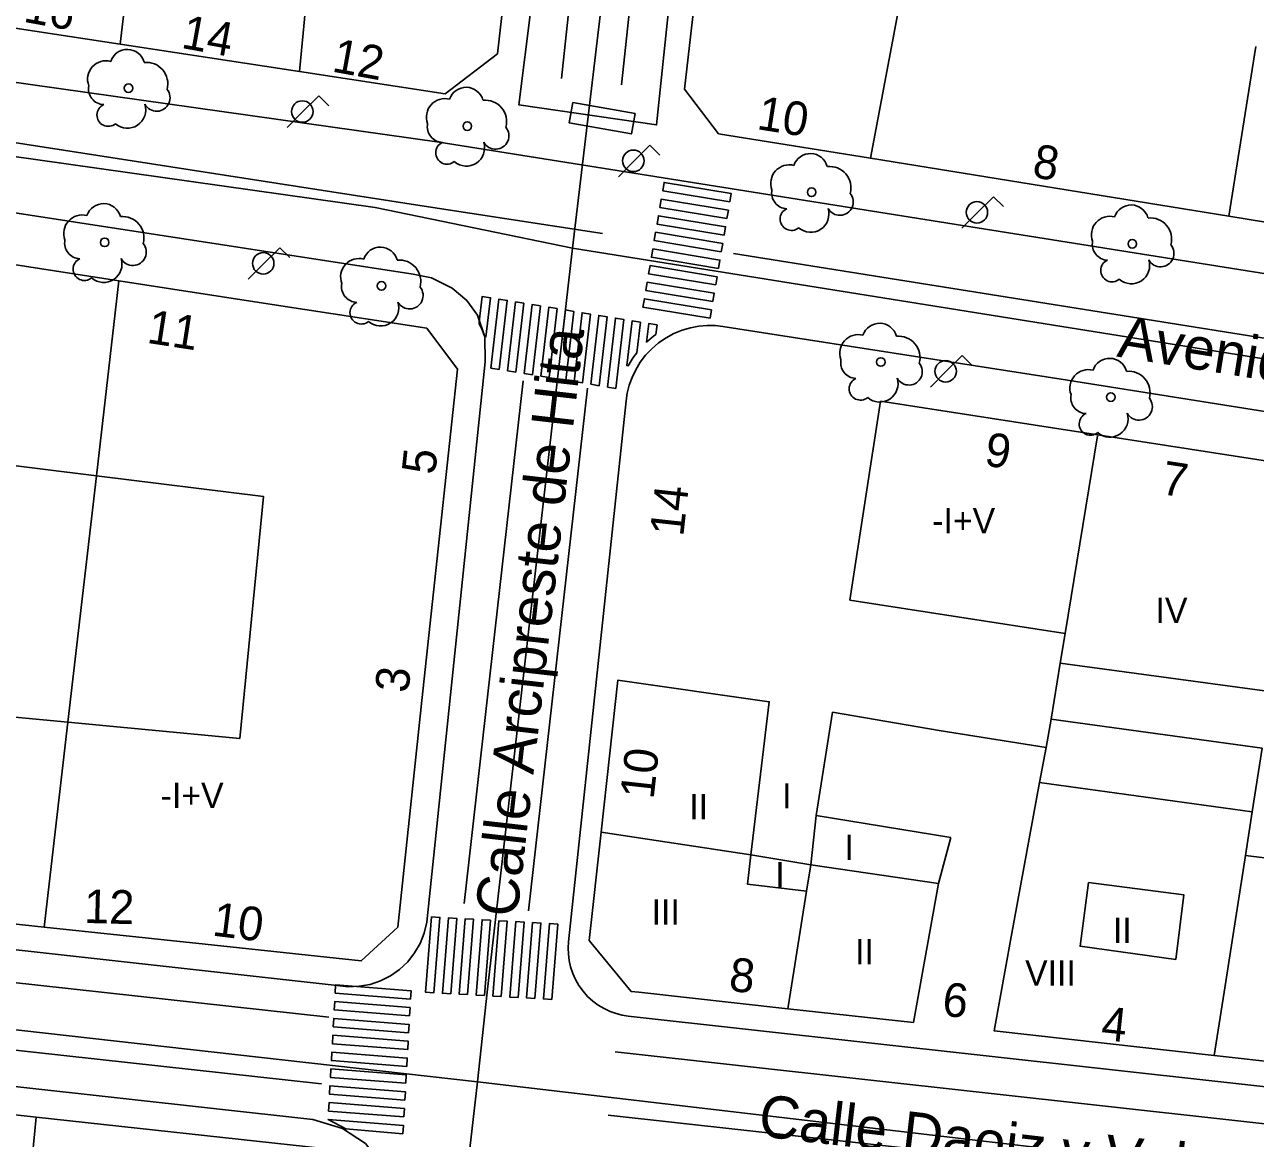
# Model space of a CAD drawing. Extents: x 282771 to 285132, y 4823109 to 4825496.
# Drawn here: x 283164.5 to 283237.5, y 4824286.9 to 4824352.9 of the extents above; entities that cross this region are included whole.
import ezdxf

# ---------------------------------------------------------------- set-up
doc = ezdxf.new("R2010")
doc.units = 0
for name, color, linetype in [('ACERA-BORDILLO', 7, 'Continuous'), ('ARBOL', 7, 'Continuous'), ('CALLE-EJE', 7, 'Continuous'), ('CALLE-TEXTO', 7, 'Continuous'), ('EDIFICIO', 7, 'Continuous'), ('EDIFICIO-PROYECTADO', 7, 'Continuous'), ('FAROLA', 7, 'Continuous'), ('INTERIOR-EDIFICIO', 7, 'Continuous'), ('MARQUESINA-BUS', 7, 'Continuous'), ('MEDIANERA', 7, 'Continuous'), ('NUM-LOCAL', 7, 'Continuous'), ('NUM-PORTAL', 7, 'Continuous'), ('NUM-VADO', 7, 'Continuous'), ('PASO-PEATONES', 7, 'Continuous'), ('SENAL-VIARIA', 7, 'Continuous'), ('TXT-ALTURA-EDIFICIO', 7, 'Continuous')]:
    doc.layers.add(name, color=color, linetype=linetype)

msp = doc.modelspace()

# ---------------------------------------------------------------- linework, layer by layer
at = {"layer": 'ACERA-BORDILLO'}
for points in [[(283204.257, 4824369.082), (283201.957, 4824346.992), (283193.797, 4824348.182), (283196.707, 4824371.452)], [(283127.812, 4824354.619), (283189.068, 4824345.967), (283271.518, 4824332.847)], [(283127.672, 4824347.349), (283187.515, 4824338.135), (283188.604, 4824337.924), (283189.834, 4824337.309), (283190.712, 4824336.571), (283191.327, 4824335.709), (283191.766, 4824334.427), (283191.783, 4824332.95), (283188.337, 4824299.711), (283188.177, 4824299.061), (283187.937, 4824298.451), (283187.607, 4824297.881), (283187.197, 4824297.361), (283186.717, 4824296.911), (283186.177, 4824296.531), (283185.587, 4824296.231), (283184.967, 4824296.021), (283184.317, 4824295.911), (283183.657, 4824295.881), (283183.007, 4824295.961), (283121.944, 4824302.739)], [(283249.853, 4824328.121), (283225.959, 4824331.907), (283205.895, 4824335.04), (283205.437, 4824335.09), (283204.959, 4824335.097), (283204.468, 4824335.057), (283203.971, 4824334.965), (283203.474, 4824334.82), (283202.988, 4824334.621), (283202.519, 4824334.368), (283202.078, 4824334.065), (283201.672, 4824333.717), (283201.307, 4824333.33), (283200.989, 4824332.912), (283200.721, 4824332.469), (283200.504, 4824332.012), (283200.338, 4824331.548), (283200.222, 4824331.085), (283200.152, 4824330.629)], [(283200.152, 4824330.629), (283196.735, 4824298.541), (283196.713, 4824298.183), (283196.724, 4824297.812), (283196.771, 4824297.433), (283196.857, 4824297.051), (283196.983, 4824296.672), (283197.149, 4824296.301), (283197.353, 4824295.946), (283197.595, 4824295.611), (283197.869, 4824295.304), (283198.172, 4824295.027), (283198.498, 4824294.786), (283198.842, 4824294.582), (283199.197, 4824294.416), (283199.556, 4824294.288), (283199.916, 4824294.197), (283200.271, 4824294.142), (283249.697, 4824288.651)], [(283123.708, 4824294.401), (283181.577, 4824288.011), (283183.327, 4824287.471), (283184.687, 4824286.581), (283185.537, 4824285.471), (283185.967, 4824284.401), (283186.047, 4824283.301), (283185.757, 4824281.051), (283182.747, 4824248.738), (283182.684, 4824248.288), (283182.577, 4824247.831), (283182.422, 4824247.373), (283182.217, 4824246.921), (283181.964, 4824246.482), (283181.661, 4824246.065), (283181.314, 4824245.677), (283180.926, 4824245.325), (283180.503, 4824245.016), (283180.053, 4824244.754), (283179.583, 4824244.543), (283179.102, 4824244.383), (283178.618, 4824244.275), (283178.137, 4824244.216)]]:
    msp.add_lwpolyline(points, dxfattribs=at)
at = {"layer": 'ARBOL'}
for centre in [(283170.635, 4824349.171), (283190.732, 4824346.925), (283211.155, 4824342.997), (283169.222, 4824340.027), (283230.176, 4824339.946), (283185.644, 4824337.444), (283215.253, 4824332.931), (283228.899, 4824330.851)]:
    msp.add_circle(centre, 0.255, dxfattribs=at)
for centre, radius, start, end in [((283170.565, 4824350.431), 1.038, 15.64228, 161.38435), ((283169.305, 4824349.701), 1.097, 75.4318, 200.55608), ((283171.695, 4824349.431), 1.272, 345.03273, 95.79925), ((283169.195, 4824349.131), 0.935, 168.59898, 268.13236), ((283190.662, 4824348.185), 1.038, 15.64228, 161.38435), ((283172.305, 4824348.601), 0.797, 208.96246, 38.99103), ((283189.402, 4824347.455), 1.097, 75.4318, 200.55608), ((283169.435, 4824347.581), 0.672, 113.73672, 309.4725), ((283170.575, 4824347.881), 1.086, 228.95447, 17.92796), ((283191.792, 4824347.185), 1.272, 345.03273, 95.79925), ((283189.292, 4824346.885), 0.935, 168.59898, 268.13236), ((283192.402, 4824346.355), 0.797, 208.96246, 38.99103), ((283189.532, 4824345.335), 0.672, 113.73672, 309.4725), ((283190.672, 4824345.635), 1.086, 228.95447, 17.92796), ((283211.085, 4824344.256), 1.038, 15.64228, 161.38435), ((283209.826, 4824343.527), 1.097, 75.4318, 200.55608), ((283212.215, 4824343.257), 1.272, 345.03273, 95.79925), ((283209.716, 4824342.957), 0.935, 168.59898, 268.13236), ((283212.825, 4824342.427), 0.797, 208.96246, 38.99103), ((283169.152, 4824341.287), 1.038, 15.64228, 161.38435), ((283209.956, 4824341.407), 0.672, 113.73672, 309.4725), ((283211.095, 4824341.707), 1.086, 228.95447, 17.92796), ((283230.106, 4824341.206), 1.038, 15.64228, 161.38435), ((283167.892, 4824340.557), 1.097, 75.4318, 200.55608), ((283170.282, 4824340.287), 1.272, 345.03273, 95.79925), ((283228.846, 4824340.476), 1.097, 75.4318, 200.55608), ((283231.236, 4824340.206), 1.272, 345.03273, 95.79925), ((283167.782, 4824339.987), 0.935, 168.59898, 268.13236), ((283170.892, 4824339.457), 0.797, 208.96246, 38.99103), ((283185.574, 4824338.704), 1.038, 15.64228, 161.38435), ((283228.736, 4824339.906), 0.935, 168.59898, 268.13236), ((283231.846, 4824339.376), 0.797, 208.96246, 38.99103), ((283168.022, 4824338.437), 0.672, 113.73672, 309.4725), ((283169.162, 4824338.737), 1.086, 228.95447, 17.92796), ((283184.314, 4824337.974), 1.097, 75.4318, 200.55608), ((283186.704, 4824337.704), 1.272, 345.03273, 95.79925), ((283230.116, 4824338.656), 1.086, 228.95447, 17.92796), ((283228.976, 4824338.356), 0.672, 113.73672, 309.4725), ((283184.204, 4824337.404), 0.935, 168.59898, 268.13236), ((283187.314, 4824336.874), 0.797, 208.96246, 38.99103), ((283184.444, 4824335.854), 0.672, 113.73672, 309.4725), ((283185.584, 4824336.154), 1.086, 228.95447, 17.92796), ((283215.183, 4824334.191), 1.038, 15.64228, 161.38435), ((283213.923, 4824333.461), 1.097, 75.4318, 200.55608), ((283216.313, 4824333.191), 1.272, 345.03273, 95.79925), ((283228.829, 4824332.111), 1.038, 15.64228, 161.38435), ((283213.813, 4824332.891), 0.935, 168.59898, 268.13236), ((283216.923, 4824332.361), 0.797, 208.96246, 38.99103), ((283227.569, 4824331.381), 1.097, 75.4318, 200.55608), ((283214.053, 4824331.341), 0.672, 113.73672, 309.4725), ((283215.193, 4824331.641), 1.086, 228.95447, 17.92796), ((283229.959, 4824331.111), 1.272, 345.03273, 95.79925), ((283227.459, 4824330.811), 0.935, 168.59898, 268.13236), ((283230.569, 4824330.281), 0.797, 208.96246, 38.99103), ((283227.699, 4824329.261), 0.672, 113.73672, 309.4725), ((283228.839, 4824329.561), 1.086, 228.95447, 17.92796)]:
    msp.add_arc(centre, radius, start, end, dxfattribs=at)
at = {"layer": 'CALLE-EJE'}
for points in [[(283201.597, 4824378.58), (283196.967, 4824339.691)], [(283196.967, 4824339.691), (283185.262, 4824342.101), (283136.138, 4824349.042), (283119.458, 4824350.58)], [(283191.327, 4824290.231), (283191.917, 4824295.551), (283196.967, 4824339.691)], [(283285.296, 4824325.541), (283196.967, 4824339.691)], [(283191.327, 4824290.231), (283144.108, 4824295.551), (283113.935, 4824298.88)], [(283185.477, 4824239.372), (283191.327, 4824290.231)], [(283252.047, 4824283.131), (283191.327, 4824290.231)]]:
    msp.add_lwpolyline(points, dxfattribs=at)
at = {"layer": 'EDIFICIO'}
for p, q in [((283207.555, 4824303.71), (283198.667, 4824305.051)), ((283210.858, 4824301.542), (283211.107, 4824303.111))]:
    msp.add_line(p, q, dxfattribs=at)
for points in [[(283147.888, 4824355.19), (283128.678, 4824357.36), (283126.188, 4824361.11), (283127.868, 4824376.76), (283131.028, 4824379.33), (283150.198, 4824377.82), (283161.548, 4824376.92), (283172.737, 4824376.04), (283183.357, 4824375.21), (283192.327, 4824374.51), (283194.797, 4824371.34), (283192.527, 4824351.211), (283189.417, 4824348.841), (283180.777, 4824350.151), (283170.137, 4824351.781), (283158.838, 4824353.51), (283151.492, 4824354.635), (283147.888, 4824355.19)], [(283266.456, 4824364.13), (283271.306, 4824350.261), (283275.216, 4824339.091), (283272.326, 4824335.691), (283257.427, 4824338.091), (283246.257, 4824339.891), (283243.277, 4824340.381), (283235.907, 4824341.571), (283214.637, 4824345.011), (283205.637, 4824346.471), (283203.607, 4824349.111), (283206.027, 4824370.17)], [(283189.137, 4824323.141), (283188.037, 4824312.861), (283186.607, 4824299.421), (283184.437, 4824297.411), (283175.187, 4824298.401), (283165.628, 4824299.421), (283149.298, 4824301.181), (283133.488, 4824302.901), (283122.804, 4824304.074), (283120.294, 4824307.282), (283121.278, 4824315.861), (283122.258, 4824324.361), (283123.198, 4824332.511), (283124.218, 4824341.351), (283127.528, 4824343.741), (283137.668, 4824342.731), (283153.898, 4824340.251), (283170.067, 4824337.741), (283179.147, 4824336.341), (283188.327, 4824334.931), (283190.147, 4824332.511), (283189.137, 4824323.141)], [(283213.427, 4824318.797), (283226.185, 4824316.822), (283225.896, 4824315.071), (283225.367, 4824311.741), (283225.057, 4824310.061), (283224.679, 4824308.001), (283222.998, 4824298.831), (283221.987, 4824293.261), (283235.037, 4824291.801), (283243.537, 4824290.851), (283251.267, 4824289.991), (283256.097, 4824295.551), (283258.477, 4824298.281), (283262.947, 4824303.431), (283264.977, 4824305.771), (283274.996, 4824317.301), (283273.496, 4824321.721), (283260.217, 4824323.721), (283248.727, 4824325.451), (283240.107, 4824326.761), (283215.247, 4824330.601), (283213.427, 4824318.797)], [(283198.667, 4824305.051), (283199.657, 4824314.061), (283208.638, 4824312.778), (283207.555, 4824303.71)], [(283211.107, 4824303.111), (283218.681, 4824302.001), (283217.187, 4824293.761)], [(283210.858, 4824301.542), (283209.907, 4824295.551), (283209.747, 4824294.571)], [(283217.187, 4824293.761), (283209.747, 4824294.571)], [(283138.168, 4824291.111), (283145.058, 4824290.351), (283152.128, 4824289.591), (283165.168, 4824288.151), (283182.227, 4824286.291), (283184.647, 4824281.791), (283183.587, 4824271.881), (283181.767, 4824254.732), (283181.067, 4824248.082), (283178.857, 4824246.282), (283160.738, 4824248.092), (283134.548, 4824250.762), (283124.338, 4824251.801), (283117.018, 4824252.551), (283114.578, 4824255.911), (283116.428, 4824273.001), (283118.338, 4824290.551), (283121.478, 4824292.951), (283138.168, 4824291.111)]]:
    msp.add_lwpolyline(points, dxfattribs=at)
at = {"layer": 'EDIFICIO-PROYECTADO'}
for points in [[(283209.747, 4824294.571), (283200.897, 4824295.551), (283200.447, 4824295.601), (283197.967, 4824298.621), (283198.667, 4824305.051)], [(283207.555, 4824303.71), (283207.347, 4824301.971), (283210.858, 4824301.542)]]:
    msp.add_lwpolyline(points, dxfattribs=at)
at = {"layer": 'FAROLA'}
for p, q in [((283181.924, 4824348.716), (283180.984, 4824347.786)), ((283182.514, 4824348.126), (283181.924, 4824348.716)), ((283180.984, 4824347.786), (283180.054, 4824346.846)), ((283201.562, 4824345.793), (283200.622, 4824344.863)), ((283202.152, 4824345.203), (283201.562, 4824345.793)), ((283200.622, 4824344.863), (283199.692, 4824343.923)), ((283221.938, 4824342.736), (283220.998, 4824341.806)), ((283222.528, 4824342.146), (283221.938, 4824342.736)), ((283220.998, 4824341.806), (283220.068, 4824340.866)), ((283179.607, 4824339.711), (283178.667, 4824338.781)), ((283180.197, 4824339.121), (283179.607, 4824339.711)), ((283178.667, 4824338.781), (283177.737, 4824337.841)), ((283220.081, 4824333.308), (283219.141, 4824332.378)), ((283220.671, 4824332.718), (283220.081, 4824333.308)), ((283219.141, 4824332.378), (283218.211, 4824331.438))]:
    msp.add_line(p, q, dxfattribs=at)
for centre in [(283180.944, 4824347.786), (283200.582, 4824344.863), (283220.958, 4824341.806), (283178.627, 4824338.781), (283219.101, 4824332.378)]:
    msp.add_circle(centre, 0.637, dxfattribs=at)
at = {"layer": 'INTERIOR-EDIFICIO'}
for points in [[(283134.439, 4824311.135), (283131.038, 4824311.651), (283131.508, 4824314.903), (283129.288, 4824315.111), (283129.898, 4824323.495), (283135.668, 4824322.841), (283136.176, 4824327.921), (283131.708, 4824328.391), (283131.986, 4824331.47), (283132.378, 4824335.821), (283136.924, 4824335.35), (283136.998, 4824336.091), (283139.148, 4824336.101), (283138.488, 4824329.691), (283147.198, 4824328.763), (283152.478, 4824328.201), (283168.728, 4824326.181), (283178.651, 4824324.947), (283177.236, 4824310.608), (283167.028, 4824311.571), (283150.698, 4824313.111), (283134.838, 4824314.591), (283134.439, 4824311.135)], [(283225.896, 4824315.071), (283238.317, 4824313.391), (283238.513, 4824314.854), (283242.932, 4824314.01), (283242.58, 4824311.139), (283251.074, 4824309.851), (283249.961, 4824302.06), (283236.885, 4824303.669), (283237.29, 4824306.261), (283224.679, 4824308.001)], [(283227.567, 4824302.071), (283233.227, 4824301.331), (283232.747, 4824297.504), (283227.078, 4824298.276), (283227.567, 4824302.071)]]:
    msp.add_lwpolyline(points, dxfattribs=at)
at = {"layer": 'MARQUESINA-BUS'}
msp.add_lwpolyline([(283200.681, 4824347.668), (283196.991, 4824348.314), (283196.78, 4824347.108), (283200.47, 4824346.462), (283200.681, 4824347.668)], dxfattribs=at)
at = {"layer": 'MEDIANERA'}
msp.add_line((283211.107, 4824303.111), (283207.555, 4824303.71), dxfattribs=at)
for points in [[(283216.867, 4824356.79), (283214.637, 4824345.011)], [(283170.382, 4824353.8), (283170.137, 4824351.781)], [(283181.157, 4824354.1), (283180.777, 4824350.151)], [(283235.907, 4824341.571), (283237.497, 4824351.651)], [(283170.067, 4824337.741), (283168.728, 4824326.181), (283167.028, 4824311.571), (283165.628, 4824299.421)], [(283228.117, 4824328.551), (283226.185, 4824316.822)], [(283212.389, 4824312.169), (283211.416, 4824306.04)], [(283212.389, 4824312.169), (283218.721, 4824311.076)], [(283237.877, 4824310.021), (283225.367, 4824311.741)], [(283218.721, 4824311.076), (283225.057, 4824310.061)], [(283237.877, 4824310.021), (283237.29, 4824306.261)], [(283211.107, 4824303.111), (283211.416, 4824306.04)], [(283219.42, 4824304.725), (283211.416, 4824306.04)], [(283219.42, 4824304.725), (283218.681, 4824302.001)], [(283236.885, 4824303.669), (283235.856, 4824297.081)], [(283235.856, 4824297.081), (283235.617, 4824295.551), (283235.037, 4824291.801)], [(283165.168, 4824288.151), (283163.987, 4824276.209)]]:
    msp.add_lwpolyline(points, dxfattribs=at)
at = {"layer": 'PASO-PEATONES'}
for points in [[(283206.3, 4824342.429), (283202.322, 4824343.087), (283202.406, 4824343.58), (283206.383, 4824342.921)], [(283206.132, 4824341.443), (283202.154, 4824342.101), (283202.238, 4824342.594), (283206.216, 4824341.935)], [(283205.965, 4824340.457), (283201.987, 4824341.115), (283202.071, 4824341.608), (283206.048, 4824340.95)], [(283205.797, 4824339.471), (283201.82, 4824340.129), (283201.903, 4824340.622), (283205.881, 4824339.964)], [(283205.63, 4824338.485), (283201.652, 4824339.143), (283201.736, 4824339.636), (283205.714, 4824338.978)], [(283205.463, 4824337.499), (283201.485, 4824338.157), (283201.568, 4824338.65), (283205.546, 4824337.992)], [(283205.295, 4824336.513), (283201.317, 4824337.172), (283201.401, 4824337.664), (283205.379, 4824337.006)], [(283191.588, 4824334.879), (283191.426, 4824335.203), (283191.439, 4824335.317), (283191.614, 4824336.821), (283192.108, 4824336.74), (283191.837, 4824334.411), (283191.769, 4824334.419)], [(283192.127, 4824332.573), (283192.602, 4824336.66), (283193.096, 4824336.579), (283192.621, 4824332.493)], [(283193.115, 4824332.412), (283193.59, 4824336.499), (283194.084, 4824336.419), (283193.609, 4824332.332)], [(283194.103, 4824332.251), (283194.578, 4824336.338), (283195.072, 4824336.258), (283194.597, 4824332.171)], [(283195.091, 4824332.09), (283195.566, 4824336.177), (283196.06, 4824336.096), (283195.585, 4824332.01)], [(283205.128, 4824335.527), (283201.15, 4824336.186), (283201.234, 4824336.679), (283205.211, 4824336.02)], [(283196.079, 4824331.929), (283196.554, 4824336.016), (283197.048, 4824335.935), (283196.573, 4824331.849)], [(283197.067, 4824331.768), (283197.542, 4824335.855), (283198.036, 4824335.774), (283197.561, 4824331.688)], [(283198.055, 4824331.607), (283198.53, 4824335.694), (283199.024, 4824335.614), (283198.549, 4824331.527)], [(283199.043, 4824331.446), (283199.518, 4824335.533), (283200.012, 4824335.453), (283199.537, 4824331.366)], [(283201, 4824335.292), (283200.789, 4824333.474), (283200.575, 4824333.193), (283200.28, 4824332.707), (283200.197, 4824332.716), (283200.506, 4824335.372)], [(283201.773, 4824334.463), (283201.366, 4824334.114), (283201.494, 4824335.211), (283201.988, 4824335.13), (283201.922, 4824334.565)], [(283188.753, 4824295.522), (283188.254, 4824295.549), (283188.609, 4824300.019), (283189.108, 4824299.991)], [(283189.752, 4824295.466), (283189.252, 4824295.493), (283189.607, 4824299.963), (283190.106, 4824299.935)], [(283190.75, 4824295.41), (283190.251, 4824295.438), (283190.606, 4824299.907), (283191.105, 4824299.879)], [(283191.749, 4824295.354), (283191.25, 4824295.382), (283191.605, 4824299.851), (283192.104, 4824299.823)], [(283192.748, 4824295.298), (283192.248, 4824295.326), (283192.603, 4824299.795), (283193.103, 4824299.767)], [(283193.746, 4824295.242), (283193.247, 4824295.27), (283193.602, 4824299.739), (283194.101, 4824299.711)], [(283194.745, 4824295.186), (283194.246, 4824295.214), (283194.601, 4824299.683), (283195.1, 4824299.655)], [(283195.744, 4824295.13), (283195.245, 4824295.158), (283195.599, 4824299.627), (283196.099, 4824299.599)], [(283187.364, 4824295.144), (283182.895, 4824295.499), (283182.923, 4824295.999), (283187.392, 4824295.644)], [(283187.308, 4824294.146), (283182.839, 4824294.501), (283182.866, 4824295), (283187.336, 4824294.645)], [(283187.252, 4824293.147), (283182.783, 4824293.502), (283182.811, 4824294.001), (283187.28, 4824293.646)], [(283187.196, 4824292.148), (283182.727, 4824292.503), (283182.755, 4824293.003), (283187.224, 4824292.648)], [(283187.14, 4824291.15), (283182.671, 4824291.504), (283182.699, 4824292.004), (283187.168, 4824291.649)], [(283187.084, 4824290.151), (283182.615, 4824290.506), (283182.643, 4824291.005), (283187.112, 4824290.65)], [(283187.028, 4824289.152), (283182.559, 4824289.507), (283182.587, 4824290.007), (283187.056, 4824289.652)], [(283186.972, 4824288.154), (283182.503, 4824288.508), (283182.531, 4824289.008), (283187, 4824288.653)], [(283186.917, 4824287.155), (283183.524, 4824287.445), (283182.475, 4824288.009), (283186.944, 4824287.654)]]:
    msp.add_lwpolyline(points, close=True, dxfattribs=at)
at = {"layer": 'SENAL-VIARIA'}
for points in [[(283198.554, 4824370.612), (283196.323, 4824349.741)], [(283202.104, 4824370.232), (283199.873, 4824349.362)], [(283136.7, 4824350.001), (283149.623, 4824348.205), (283162.44, 4824346.161), (283188.171, 4824342.172), (283198.754, 4824340.543)], [(283206.528, 4824339.365), (283253.237, 4824331.906)], [(283194.049, 4824331.816), (283190.553, 4824300.816)], [(283197.857, 4824331.386), (283194.36, 4824300.386)], [(283182.525, 4824294.066), (283123.35, 4824300.578)], [(283182.091, 4824290.117), (283122.916, 4824296.629)], [(283199.504, 4824292.01), (283243.206, 4824287.18)], [(283199.09, 4824288.265), (283239.148, 4824283.839), (283238.96, 4824281.578)]]:
    msp.add_lwpolyline(points, dxfattribs=at)

# ---------------------------------------------------------------- texts
at = {"layer": 'CALLE-TEXTO'}
for s, rotation, p in [('Avenida de Galicia', 350.89888, (283229.207, 4824333.26)), ('Calle Arcipreste de Hita', 83.4733, (283193.677, 4824299.937)), ('Calle Daoiz y Velarde', 353.3308, (283207.929, 4824287.031))]:
    msp.add_text(s, height=2.5, rotation=rotation, dxfattribs=at).set_placement(p)
at = {"layer": 'NUM-LOCAL'}
for s, rotation, p in [('12', 349.66004, (283182.645, 4824350.166)), ('10', 350.92004, (283207.85, 4824346.751)), ('11', 351.19004, (283171.673, 4824334.076)), ('14', 83.73004, (283203.539, 4824322.54)), ('3', 83.89004, (283187.231, 4824313.265))]:
    msp.add_text(s, height=2, rotation=rotation, dxfattribs=at).set_placement(p)
at = {"layer": 'NUM-PORTAL'}
for s, rotation, p in [('16', 349.66004, (283164.346, 4824353.119)), ('14', 349.66004, (283173.707, 4824351.567)), ('8', 350.92004, (283224.185, 4824343.905)), ('9', 351.30004, (283221.337, 4824326.807)), ('5', 83.89004, (283188.821, 4824326.207)), ('7', 351.30004, (283231.829, 4824325.107)), ('10', 83.73004, (283201.779, 4824306.959)), ('10', 352.815, (283175.553, 4824298.921)), ('8', 353.99004, (283206.199, 4824295.643)), ('6', 353.99004, (283218.846, 4824294.172)), ('4', 353.99004, (283228.273, 4824292.74))]:
    msp.add_text(s, height=2, rotation=rotation, dxfattribs=at).set_placement(p)
at = {"layer": 'NUM-VADO'}
msp.add_text('12', height=2, rotation=358.46249, dxfattribs=at).set_placement((283167.982, 4824299.666))
at = {"layer": 'TXT-ALTURA-EDIFICIO'}
for s, p in [('-I+V', (283218.306, 4824322.769)), ('IV', (283231.553, 4824317.447)), ('-I+V', (283172.542, 4824306.478)), ('I', (283209.406, 4824306.451)), ('II', (283203.896, 4824305.811)), ('I', (283213.099, 4824303.39)), ('I', (283208.996, 4824301.781)), ('III', (283201.665, 4824299.561)), ('II', (283229.025, 4824298.481)), ('II', (283213.736, 4824297.211)), ('VIII', (283223.815, 4824295.952))]:
    msp.add_text(s, height=1.5, rotation=0.00004, dxfattribs=at).set_placement(p)

doc.saveas('drawing.dxf')
